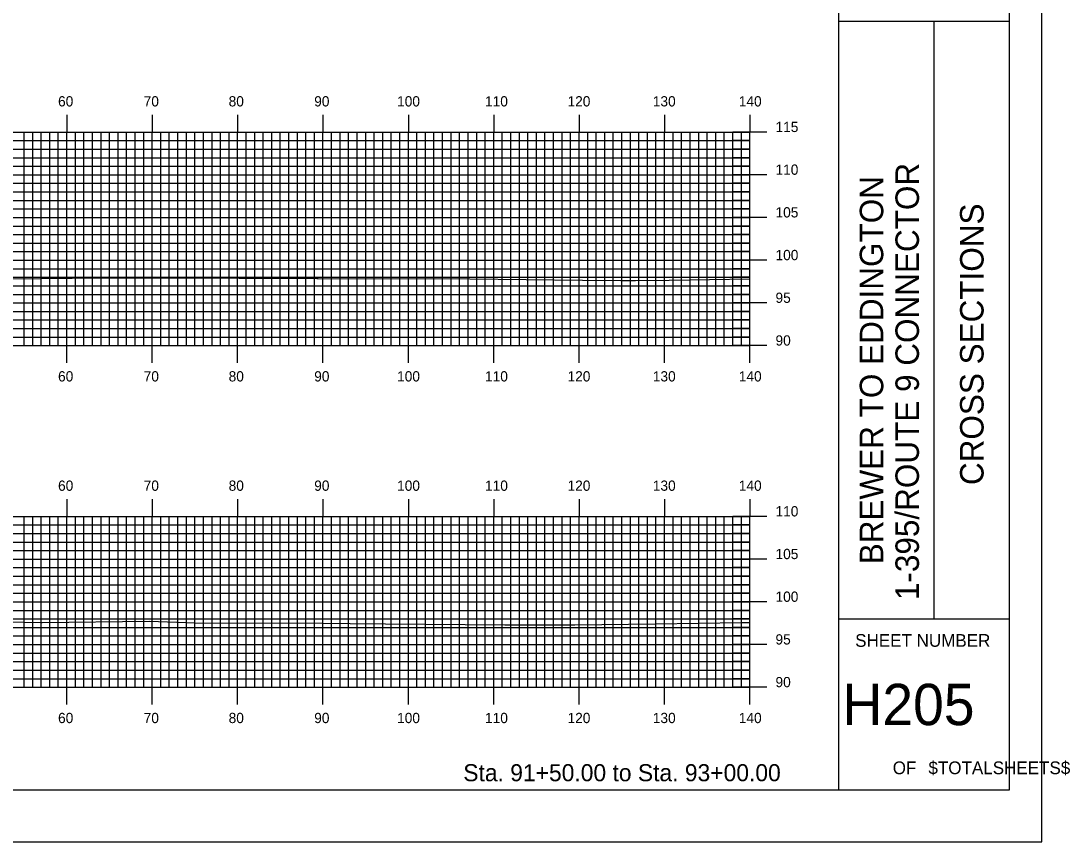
# Model space of a CAD drawing. Extents: x 1764939 to 1765282, y 442591 to 442811.
# Drawn here: x 1765159.5 to 1765282.4, y 442590.5 to 442686.7 of the extents above; entities that cross this region are included whole.
import ezdxf

# ---------------------------------------------------------------- set-up
doc = ezdxf.new("R2010")
doc.units = 0
for name, color, linetype in [('BORDER', 7, 'Continuous'), ('H_V ANNOTATION', 7, 'Continuous'), ('MAJOR', 7, 'Continuous'), ('MINOR', 7, 'Continuous'), ('PLOT BOUNDARY', 7, 'Continuous'), ('S_Roadway_Centerline', 7, 'Continuous')]:
    doc.layers.add(name, color=color, linetype=linetype)

msp = doc.modelspace()

# ---------------------------------------------------------------- linework, layer by layer
at = {"layer": 'BORDER'}
for p, q in [((1765255.26, 442596.67), (1765255.26, 442806.67)), ((1765255.26, 442686.67), (1765275.26, 442686.67)), ((1765266.44, 442616.67), (1765266.44, 442686.67)), ((1765255.26, 442616.67), (1765275.26, 442616.67))]:
    msp.add_line(p, q, dxfattribs=at)
msp.add_lwpolyline([(1764955.26, 442596.67), (1765275.26, 442596.67), (1765275.26, 442806.67), (1764955.26, 442806.67)], close=True, dxfattribs=at)
at = {"layer": 'MAJOR'}
for p, q in [((1765164.86, 442675.67), (1765164.86, 442673.67)), ((1765174.86, 442675.67), (1765174.86, 442673.67)), ((1765184.86, 442675.67), (1765184.86, 442673.67)), ((1765194.86, 442675.67), (1765194.86, 442673.67)), ((1765204.86, 442675.67), (1765204.86, 442673.67)), ((1765214.86, 442675.67), (1765214.86, 442673.67)), ((1765224.86, 442675.67), (1765224.86, 442673.67)), ((1765234.86, 442675.67), (1765234.86, 442673.67)), ((1765244.86, 442675.67), (1765244.86, 442673.67)), ((1764964.86, 442673.67), (1765244.86, 442673.67)), ((1764964.86, 442673.67), (1765244.86, 442673.67)), ((1765164.86, 442648.67), (1765164.86, 442673.67)), ((1765174.86, 442648.67), (1765174.86, 442673.67)), ((1765184.86, 442648.67), (1765184.86, 442673.67)), ((1765194.86, 442648.67), (1765194.86, 442673.67)), ((1765204.86, 442648.67), (1765204.86, 442673.67)), ((1765214.86, 442648.67), (1765214.86, 442673.67)), ((1765224.86, 442648.67), (1765224.86, 442673.67)), ((1765234.86, 442648.67), (1765234.86, 442673.67)), ((1765246.86, 442673.67), (1765242.85, 442673.67)), ((1765244.86, 442648.67), (1765244.86, 442673.67)), ((1765244.86, 442648.67), (1765244.86, 442673.67)), ((1764964.86, 442668.67), (1765244.86, 442668.67)), ((1765246.86, 442668.67), (1765242.85, 442668.67)), ((1764964.86, 442663.67), (1765244.86, 442663.67)), ((1765246.86, 442663.67), (1765242.85, 442663.67)), ((1764964.86, 442658.67), (1765244.86, 442658.67)), ((1765246.86, 442658.67), (1765242.85, 442658.67)), ((1764964.86, 442653.67), (1765244.86, 442653.67)), ((1765246.86, 442653.67), (1765242.85, 442653.67)), ((1764964.86, 442648.67), (1765244.86, 442648.67)), ((1764964.86, 442648.67), (1765244.86, 442648.67)), ((1765164.86, 442646.66), (1765164.86, 442648.67)), ((1765174.86, 442646.66), (1765174.86, 442648.67)), ((1765184.86, 442646.66), (1765184.86, 442648.67)), ((1765194.86, 442646.66), (1765194.86, 442648.67)), ((1765204.86, 442646.66), (1765204.86, 442648.67)), ((1765214.86, 442646.66), (1765214.86, 442648.67)), ((1765224.86, 442646.66), (1765224.86, 442648.67)), ((1765234.86, 442646.66), (1765234.86, 442648.67)), ((1765246.86, 442648.67), (1765242.85, 442648.67)), ((1765244.86, 442646.66), (1765244.86, 442648.67)), ((1765164.86, 442630.67), (1765164.86, 442628.67)), ((1765174.86, 442630.67), (1765174.86, 442628.67)), ((1765184.86, 442630.67), (1765184.86, 442628.67)), ((1765194.86, 442630.67), (1765194.86, 442628.67)), ((1765204.86, 442630.67), (1765204.86, 442628.67)), ((1765214.86, 442630.67), (1765214.86, 442628.67)), ((1765224.86, 442630.67), (1765224.86, 442628.67)), ((1765234.86, 442630.67), (1765234.86, 442628.67)), ((1765244.86, 442630.67), (1765244.86, 442628.67)), ((1764964.86, 442628.67), (1765244.86, 442628.67)), ((1764964.86, 442628.67), (1765244.86, 442628.67)), ((1765164.86, 442608.67), (1765164.86, 442628.67)), ((1765174.86, 442608.67), (1765174.86, 442628.67)), ((1765184.86, 442608.67), (1765184.86, 442628.67)), ((1765194.86, 442608.67), (1765194.86, 442628.67)), ((1765204.86, 442608.67), (1765204.86, 442628.67)), ((1765214.86, 442608.67), (1765214.86, 442628.67)), ((1765224.86, 442608.67), (1765224.86, 442628.67)), ((1765234.86, 442608.67), (1765234.86, 442628.67)), ((1765246.86, 442628.67), (1765242.85, 442628.67)), ((1765244.86, 442608.67), (1765244.86, 442628.67)), ((1765244.86, 442608.67), (1765244.86, 442628.67)), ((1764964.86, 442623.67), (1765244.86, 442623.67)), ((1765246.86, 442623.67), (1765242.85, 442623.67)), ((1764964.86, 442618.67), (1765244.86, 442618.67)), ((1765246.86, 442618.67), (1765242.85, 442618.67)), ((1764964.86, 442613.67), (1765244.86, 442613.67)), ((1765246.86, 442613.67), (1765242.85, 442613.67)), ((1764964.86, 442608.67), (1765244.86, 442608.67)), ((1764964.86, 442608.67), (1765244.86, 442608.67)), ((1765164.86, 442606.66), (1765164.86, 442608.67)), ((1765174.86, 442606.66), (1765174.86, 442608.67)), ((1765184.86, 442606.66), (1765184.86, 442608.67)), ((1765194.86, 442606.66), (1765194.86, 442608.67)), ((1765204.86, 442606.66), (1765204.86, 442608.67)), ((1765214.86, 442606.66), (1765214.86, 442608.67)), ((1765224.86, 442606.66), (1765224.86, 442608.67)), ((1765234.86, 442606.66), (1765234.86, 442608.67)), ((1765246.86, 442608.67), (1765242.85, 442608.67)), ((1765244.86, 442606.66), (1765244.86, 442608.67))]:
    msp.add_line(p, q, dxfattribs=at)
at = {"layer": 'MINOR'}
for p, q in [((1764964.86, 442672.67), (1765244.86, 442672.67)), ((1765159.86, 442648.67), (1765159.86, 442673.67)), ((1765160.86, 442648.67), (1765160.86, 442673.67)), ((1765161.86, 442648.67), (1765161.86, 442673.67)), ((1765162.86, 442648.67), (1765162.86, 442673.67)), ((1765163.86, 442648.67), (1765163.86, 442673.67)), ((1765165.86, 442648.67), (1765165.86, 442673.67)), ((1765166.86, 442648.67), (1765166.86, 442673.67)), ((1765167.86, 442648.67), (1765167.86, 442673.67)), ((1765168.86, 442648.67), (1765168.86, 442673.67)), ((1765169.86, 442648.67), (1765169.86, 442673.67)), ((1765170.86, 442648.67), (1765170.86, 442673.67)), ((1765171.86, 442648.67), (1765171.86, 442673.67)), ((1765172.86, 442648.67), (1765172.86, 442673.67)), ((1765173.86, 442648.67), (1765173.86, 442673.67)), ((1765175.86, 442648.67), (1765175.86, 442673.67)), ((1765176.86, 442648.67), (1765176.86, 442673.67)), ((1765177.86, 442648.67), (1765177.86, 442673.67)), ((1765178.86, 442648.67), (1765178.86, 442673.67)), ((1765179.86, 442648.67), (1765179.86, 442673.67)), ((1765180.86, 442648.67), (1765180.86, 442673.67)), ((1765181.86, 442648.67), (1765181.86, 442673.67)), ((1765182.86, 442648.67), (1765182.86, 442673.67)), ((1765183.86, 442648.67), (1765183.86, 442673.67)), ((1765185.86, 442648.67), (1765185.86, 442673.67)), ((1765186.86, 442648.67), (1765186.86, 442673.67)), ((1765187.86, 442648.67), (1765187.86, 442673.67)), ((1765188.86, 442648.67), (1765188.86, 442673.67)), ((1765189.86, 442648.67), (1765189.86, 442673.67)), ((1765190.86, 442648.67), (1765190.86, 442673.67)), ((1765191.86, 442648.67), (1765191.86, 442673.67)), ((1765192.86, 442648.67), (1765192.86, 442673.67)), ((1765193.86, 442648.67), (1765193.86, 442673.67)), ((1765195.86, 442648.67), (1765195.86, 442673.67)), ((1765196.86, 442648.67), (1765196.86, 442673.67)), ((1765197.86, 442648.67), (1765197.86, 442673.67)), ((1765198.86, 442648.67), (1765198.86, 442673.67)), ((1765199.86, 442648.67), (1765199.86, 442673.67)), ((1765200.86, 442648.67), (1765200.86, 442673.67)), ((1765201.86, 442648.67), (1765201.86, 442673.67)), ((1765202.86, 442648.67), (1765202.86, 442673.67)), ((1765203.86, 442648.67), (1765203.86, 442673.67)), ((1765205.86, 442648.67), (1765205.86, 442673.67)), ((1765206.86, 442648.67), (1765206.86, 442673.67)), ((1765207.86, 442648.67), (1765207.86, 442673.67)), ((1765208.86, 442648.67), (1765208.86, 442673.67)), ((1765209.86, 442648.67), (1765209.86, 442673.67)), ((1765210.86, 442648.67), (1765210.86, 442673.67)), ((1765211.86, 442648.67), (1765211.86, 442673.67)), ((1765212.86, 442648.67), (1765212.86, 442673.67)), ((1765213.86, 442648.67), (1765213.86, 442673.67)), ((1765215.86, 442648.67), (1765215.86, 442673.67)), ((1765216.86, 442648.67), (1765216.86, 442673.67)), ((1765217.86, 442648.67), (1765217.86, 442673.67)), ((1765218.86, 442648.67), (1765218.86, 442673.67)), ((1765219.86, 442648.67), (1765219.86, 442673.67)), ((1765220.86, 442648.67), (1765220.86, 442673.67)), ((1765221.86, 442648.67), (1765221.86, 442673.67)), ((1765222.86, 442648.67), (1765222.86, 442673.67)), ((1765223.86, 442648.67), (1765223.86, 442673.67)), ((1765225.86, 442648.67), (1765225.86, 442673.67)), ((1765226.86, 442648.67), (1765226.86, 442673.67)), ((1765227.86, 442648.67), (1765227.86, 442673.67)), ((1765228.86, 442648.67), (1765228.86, 442673.67)), ((1765229.86, 442648.67), (1765229.86, 442673.67)), ((1765230.86, 442648.67), (1765230.86, 442673.67)), ((1765231.86, 442648.67), (1765231.86, 442673.67)), ((1765232.86, 442648.67), (1765232.86, 442673.67)), ((1765233.86, 442648.67), (1765233.86, 442673.67)), ((1765235.86, 442648.67), (1765235.86, 442673.67)), ((1765236.86, 442648.67), (1765236.86, 442673.67)), ((1765237.86, 442648.67), (1765237.86, 442673.67)), ((1765238.86, 442648.67), (1765238.86, 442673.67)), ((1765239.86, 442648.67), (1765239.86, 442673.67)), ((1765240.86, 442648.67), (1765240.86, 442673.67)), ((1765241.86, 442648.67), (1765241.86, 442673.67)), ((1765244.86, 442672.67), (1765242.85, 442672.67)), ((1765242.86, 442648.67), (1765242.86, 442673.67)), ((1765243.86, 442648.67), (1765243.86, 442673.67)), ((1764964.86, 442671.67), (1765244.86, 442671.67)), ((1765244.86, 442671.67), (1765242.85, 442671.67)), ((1764964.86, 442670.67), (1765244.86, 442670.67)), ((1765244.86, 442670.67), (1765242.85, 442670.67)), ((1764964.86, 442669.67), (1765244.86, 442669.67)), ((1765244.86, 442669.67), (1765242.85, 442669.67)), ((1764964.86, 442667.67), (1765244.86, 442667.67)), ((1764964.86, 442666.67), (1765244.86, 442666.67)), ((1765244.86, 442667.67), (1765242.85, 442667.67)), ((1765244.86, 442666.67), (1765242.85, 442666.67)), ((1764964.86, 442665.67), (1765244.86, 442665.67)), ((1765244.86, 442665.67), (1765242.85, 442665.67)), ((1764964.86, 442664.67), (1765244.86, 442664.67)), ((1765244.86, 442664.67), (1765242.85, 442664.67)), ((1764964.86, 442662.67), (1765244.86, 442662.67)), ((1764964.86, 442661.67), (1765244.86, 442661.67)), ((1765244.86, 442662.67), (1765242.85, 442662.67)), ((1765244.86, 442661.67), (1765242.85, 442661.67)), ((1764964.86, 442660.67), (1765244.86, 442660.67)), ((1765244.86, 442660.67), (1765242.85, 442660.67)), ((1764964.86, 442659.67), (1765244.86, 442659.67)), ((1765244.86, 442659.67), (1765242.85, 442659.67)), ((1764964.86, 442657.67), (1765244.86, 442657.67)), ((1765244.86, 442657.67), (1765242.85, 442657.67)), ((1764964.86, 442656.67), (1765244.86, 442656.67)), ((1764964.86, 442655.67), (1765244.86, 442655.67)), ((1765244.86, 442656.67), (1765242.85, 442656.67)), ((1765244.86, 442655.67), (1765242.85, 442655.67)), ((1764964.86, 442654.67), (1765244.86, 442654.67)), ((1765244.86, 442654.67), (1765242.85, 442654.67)), ((1764964.86, 442652.67), (1765244.86, 442652.67)), ((1765244.86, 442652.67), (1765242.85, 442652.67)), ((1764964.86, 442651.67), (1765244.86, 442651.67)), ((1764964.86, 442650.67), (1765244.86, 442650.67)), ((1765244.86, 442651.67), (1765242.85, 442651.67)), ((1765244.86, 442650.67), (1765242.85, 442650.67)), ((1764964.86, 442649.67), (1765244.86, 442649.67)), ((1765244.86, 442649.67), (1765242.85, 442649.67)), ((1765159.86, 442608.67), (1765159.86, 442628.67)), ((1765160.86, 442608.67), (1765160.86, 442628.67)), ((1765161.86, 442608.67), (1765161.86, 442628.67)), ((1765162.86, 442608.67), (1765162.86, 442628.67)), ((1765163.86, 442608.67), (1765163.86, 442628.67)), ((1765165.86, 442608.67), (1765165.86, 442628.67)), ((1765166.86, 442608.67), (1765166.86, 442628.67)), ((1765167.86, 442608.67), (1765167.86, 442628.67)), ((1765168.86, 442608.67), (1765168.86, 442628.67)), ((1765169.86, 442608.67), (1765169.86, 442628.67)), ((1765170.86, 442608.67), (1765170.86, 442628.67)), ((1765171.86, 442608.67), (1765171.86, 442628.67)), ((1765172.86, 442608.67), (1765172.86, 442628.67)), ((1765173.86, 442608.67), (1765173.86, 442628.67)), ((1765175.86, 442608.67), (1765175.86, 442628.67)), ((1765176.86, 442608.67), (1765176.86, 442628.67)), ((1765177.86, 442608.67), (1765177.86, 442628.67)), ((1765178.86, 442608.67), (1765178.86, 442628.67)), ((1765179.86, 442608.67), (1765179.86, 442628.67)), ((1765180.86, 442608.67), (1765180.86, 442628.67)), ((1765181.86, 442608.67), (1765181.86, 442628.67)), ((1765182.86, 442608.67), (1765182.86, 442628.67)), ((1765183.86, 442608.67), (1765183.86, 442628.67)), ((1765185.86, 442608.67), (1765185.86, 442628.67)), ((1765186.86, 442608.67), (1765186.86, 442628.67)), ((1765187.86, 442608.67), (1765187.86, 442628.67)), ((1765188.86, 442608.67), (1765188.86, 442628.67)), ((1765189.86, 442608.67), (1765189.86, 442628.67)), ((1765190.86, 442608.67), (1765190.86, 442628.67)), ((1765191.86, 442608.67), (1765191.86, 442628.67)), ((1765192.86, 442608.67), (1765192.86, 442628.67)), ((1765193.86, 442608.67), (1765193.86, 442628.67)), ((1765195.86, 442608.67), (1765195.86, 442628.67)), ((1765196.86, 442608.67), (1765196.86, 442628.67)), ((1765197.86, 442608.67), (1765197.86, 442628.67)), ((1765198.86, 442608.67), (1765198.86, 442628.67)), ((1765199.86, 442608.67), (1765199.86, 442628.67)), ((1765200.86, 442608.67), (1765200.86, 442628.67)), ((1765201.86, 442608.67), (1765201.86, 442628.67)), ((1765202.86, 442608.67), (1765202.86, 442628.67)), ((1765203.86, 442608.67), (1765203.86, 442628.67)), ((1765205.86, 442608.67), (1765205.86, 442628.67)), ((1765206.86, 442608.67), (1765206.86, 442628.67)), ((1765207.86, 442608.67), (1765207.86, 442628.67)), ((1765208.86, 442608.67), (1765208.86, 442628.67)), ((1765209.86, 442608.67), (1765209.86, 442628.67)), ((1765210.86, 442608.67), (1765210.86, 442628.67)), ((1765211.86, 442608.67), (1765211.86, 442628.67)), ((1765212.86, 442608.67), (1765212.86, 442628.67)), ((1765213.86, 442608.67), (1765213.86, 442628.67)), ((1765215.86, 442608.67), (1765215.86, 442628.67)), ((1765216.86, 442608.67), (1765216.86, 442628.67)), ((1765217.86, 442608.67), (1765217.86, 442628.67)), ((1765218.86, 442608.67), (1765218.86, 442628.67)), ((1765219.86, 442608.67), (1765219.86, 442628.67)), ((1765220.86, 442608.67), (1765220.86, 442628.67)), ((1765221.86, 442608.67), (1765221.86, 442628.67)), ((1765222.86, 442608.67), (1765222.86, 442628.67)), ((1765223.86, 442608.67), (1765223.86, 442628.67)), ((1765225.86, 442608.67), (1765225.86, 442628.67)), ((1765226.86, 442608.67), (1765226.86, 442628.67)), ((1765227.86, 442608.67), (1765227.86, 442628.67)), ((1765228.86, 442608.67), (1765228.86, 442628.67)), ((1765229.86, 442608.67), (1765229.86, 442628.67)), ((1765230.86, 442608.67), (1765230.86, 442628.67)), ((1765231.86, 442608.67), (1765231.86, 442628.67)), ((1765232.86, 442608.67), (1765232.86, 442628.67)), ((1765233.86, 442608.67), (1765233.86, 442628.67)), ((1765235.86, 442608.67), (1765235.86, 442628.67)), ((1765236.86, 442608.67), (1765236.86, 442628.67)), ((1765237.86, 442608.67), (1765237.86, 442628.67)), ((1765238.86, 442608.67), (1765238.86, 442628.67)), ((1765239.86, 442608.67), (1765239.86, 442628.67)), ((1765240.86, 442608.67), (1765240.86, 442628.67)), ((1765241.86, 442608.67), (1765241.86, 442628.67)), ((1765242.86, 442608.67), (1765242.86, 442628.67)), ((1765243.86, 442608.67), (1765243.86, 442628.67)), ((1764964.86, 442627.67), (1765244.86, 442627.67)), ((1765244.86, 442627.67), (1765242.85, 442627.67)), ((1764964.86, 442626.67), (1765244.86, 442626.67)), ((1765244.86, 442626.67), (1765242.85, 442626.67)), ((1764964.86, 442625.67), (1765244.86, 442625.67)), ((1765244.86, 442625.67), (1765242.85, 442625.67)), ((1764964.86, 442624.67), (1765244.86, 442624.67)), ((1765244.86, 442624.67), (1765242.85, 442624.67)), ((1764964.86, 442622.67), (1765244.86, 442622.67)), ((1765244.86, 442622.67), (1765242.85, 442622.67)), ((1764964.86, 442621.67), (1765244.86, 442621.67)), ((1765244.86, 442621.67), (1765242.85, 442621.67)), ((1764964.86, 442620.67), (1765244.86, 442620.67)), ((1765244.86, 442620.67), (1765242.85, 442620.67)), ((1764964.86, 442619.67), (1765244.86, 442619.67)), ((1765244.86, 442619.67), (1765242.85, 442619.67)), ((1764964.86, 442617.67), (1765244.86, 442617.67)), ((1765244.86, 442617.67), (1765242.85, 442617.67)), ((1764964.86, 442616.67), (1765244.86, 442616.67)), ((1765244.86, 442616.67), (1765242.85, 442616.67)), ((1764964.86, 442615.67), (1765244.86, 442615.67)), ((1765244.86, 442615.67), (1765242.85, 442615.67)), ((1764964.86, 442614.67), (1765244.86, 442614.67)), ((1765244.86, 442614.67), (1765242.85, 442614.67)), ((1764964.86, 442612.67), (1765244.86, 442612.67)), ((1765244.86, 442612.67), (1765242.85, 442612.67)), ((1764964.86, 442611.67), (1765244.86, 442611.67)), ((1765244.86, 442611.67), (1765242.85, 442611.67)), ((1764964.86, 442610.67), (1765244.86, 442610.67)), ((1765244.86, 442610.67), (1765242.85, 442610.67)), ((1764964.86, 442609.67), (1765244.86, 442609.67)), ((1765244.86, 442609.67), (1765242.85, 442609.67))]:
    msp.add_line(p, q, dxfattribs=at)
at = {"layer": 'PLOT BOUNDARY'}
msp.add_lwpolyline([(1764939.07, 442590.55), (1765279.07, 442590.55), (1765279.07, 442810.55), (1764939.07, 442810.55)], close=True, dxfattribs=at)
at = {"layer": 'S_Roadway_Centerline'}
for points in [[(1765158.34, 442656.47), (1765169.05, 442656.61), (1765175.89, 442656.59), (1765194.15, 442656.54), (1765194.22, 442656.54), (1765194.31, 442656.54), (1765212.05, 442656.47), (1765225.26, 442656.33), (1765229.74, 442656.3), (1765231.48, 442656.29), (1765235.42, 442656.34), (1765244.86, 442656.47)], [(1765149.43, 442616.47), (1765161.88, 442616.23), (1765161.93, 442616.23), (1765161.95, 442616.23), (1765174.5, 442616.39), (1765179.88, 442616.22), (1765194.77, 442616.16), (1765198.03, 442616.14), (1765202.18, 442616.09), (1765216.17, 442615.99), (1765224.34, 442615.96), (1765233.81, 442616.1), (1765243.89, 442616.24), (1765244.86, 442616.25)]]:
    msp.add_lwpolyline(points, dxfattribs=at)

# ---------------------------------------------------------------- texts
at = {"layer": 'BORDER'}
for s, p in [('1-395/ROUTE 9 CONNECTOR', (1765264.66, 442618.87)), ('BREWER TO EDDINGTON', (1765260.48, 442623.07)), ('CROSS SECTIONS', (1765272.23, 442632.34))]:
    msp.add_text(s, height=2.7557, rotation=90, dxfattribs=at).set_placement(p)
for s, height, p in [('SHEET NUMBER', 1.4905, (1765257.19, 442613.4)), ('H205', 4.839, (1765255.7, 442604.23)), ('OF', 1.491, (1765261.59, 442598.49)), ('$TOTALSHEETS$', 1.4905, (1765265.77, 442598.49))]:
    msp.add_text(s, height=height, dxfattribs=at).set_placement(p)
at = {"layer": 'H_V ANNOTATION'}
for s, height, p in [('60', 1.2, (1765163.83, 442676.67)), ('70', 1.2, (1765173.86, 442676.67)), ('80', 1.2, (1765183.81, 442676.67)), ('90', 1.2, (1765193.83, 442676.67)), ('100', 1.2, (1765203.54, 442676.67)), ('110', 1.2, (1765213.84, 442676.67)), ('120', 1.2, (1765223.5, 442676.67)), ('130', 1.2, (1765233.49, 442676.67)), ('140', 1.2, (1765243.56, 442676.67)), ('115', 1.2, (1765247.86, 442673.67)), ('110', 1.2, (1765247.86, 442668.67)), ('105', 1.2, (1765247.86, 442663.67)), ('100', 1.2, (1765247.86, 442658.67)), ('95', 1.2, (1765247.86, 442653.67)), ('90', 1.2, (1765247.86, 442648.67)), ('60', 1.2, (1765163.83, 442644.47)), ('70', 1.2, (1765173.86, 442644.47)), ('80', 1.2, (1765183.81, 442644.47)), ('90', 1.2, (1765193.83, 442644.47)), ('100', 1.2, (1765203.54, 442644.47)), ('110', 1.2, (1765213.84, 442644.47)), ('120', 1.2, (1765223.5, 442644.47)), ('130', 1.2, (1765233.49, 442644.47)), ('140', 1.2, (1765243.56, 442644.47)), ('60', 1.2, (1765163.83, 442631.67)), ('70', 1.2, (1765173.86, 442631.67)), ('80', 1.2, (1765183.81, 442631.67)), ('90', 1.2, (1765193.83, 442631.67)), ('100', 1.2, (1765203.54, 442631.67)), ('110', 1.2, (1765213.84, 442631.67)), ('120', 1.2, (1765223.5, 442631.67)), ('130', 1.2, (1765233.49, 442631.67)), ('140', 1.2, (1765243.56, 442631.67)), ('110', 1.2, (1765247.86, 442628.67)), ('105', 1.2, (1765247.86, 442623.67)), ('100', 1.2, (1765247.86, 442618.67)), ('95', 1.2, (1765247.86, 442613.67)), ('90', 1.2, (1765247.86, 442608.67)), ('60', 1.2, (1765163.83, 442604.47)), ('70', 1.2, (1765173.86, 442604.47)), ('80', 1.2, (1765183.81, 442604.47)), ('90', 1.2, (1765193.83, 442604.47)), ('100', 1.2, (1765203.54, 442604.47)), ('110', 1.2, (1765213.84, 442604.47)), ('120', 1.2, (1765223.5, 442604.47)), ('130', 1.2, (1765233.49, 442604.47)), ('140', 1.2, (1765243.56, 442604.47)), ('Sta. 91+50.00 to Sta. 93+00.00', 2.0004, (1765211.29, 442597.66))]:
    msp.add_text(s, height=height, dxfattribs=at).set_placement(p)

doc.saveas('drawing.dxf')
